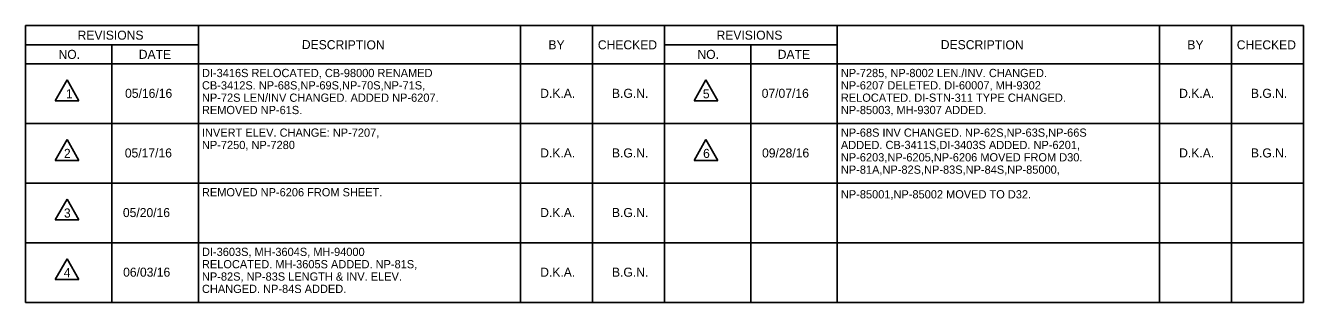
# Model space of a CAD drawing. Extents: x 260980 to 263829, y 322034 to 323393.
# Drawn here: x 263208 to 263829, y 322034 to 322169 of the extents above; entities that cross this region are included whole.
import ezdxf

# ---------------------------------------------------------------- set-up
doc = ezdxf.new("R2010")
doc.units = 0
doc.layers.add('RD_SHT_TX', color=7, linetype='Continuous')

msp = doc.modelspace()

# ---------------------------------------------------------------- linework, layer by layer
at = {"layer": 'RD_SHT_TX'}
for p, q in [((263208.14, 322034.07), (263208.14, 322168.77)), ((263208.14, 322168.77), (263518.73, 322168.77)), ((263292.13, 322034.07), (263292.13, 322168.77)), ((263448.73, 322034.07), (263448.73, 322168.77)), ((263483.73, 322034.07), (263483.73, 322168.77)), ((263518.73, 322034.07), (263518.73, 322168.77)), ((263518.73, 322168.77), (263829.33, 322168.77)), ((263602.73, 322034.07), (263602.73, 322168.77)), ((263759.33, 322034.07), (263759.33, 322168.77)), ((263794.33, 322034.07), (263794.33, 322168.77)), ((263829.33, 322034.07), (263829.33, 322168.76)), ((263292.13, 322159.42), (263208.13, 322159.42)), ((263250.13, 322034.07), (263250.13, 322159.42)), ((263602.73, 322159.42), (263518.73, 322159.42)), ((263560.73, 322034.07), (263560.73, 322159.42)), ((263518.73, 322150.07), (263208.13, 322150.07)), ((263829.33, 322150.07), (263518.73, 322150.07)), ((263228.3, 322142.33), (263222.6, 322132.19)), ((263233.99, 322132.19), (263228.3, 322142.33)), ((263538.89, 322142.33), (263533.2, 322132.19)), ((263544.59, 322132.19), (263538.89, 322142.33)), ((263222.6, 322132.19), (263233.99, 322132.19)), ((263533.2, 322132.19), (263544.59, 322132.19)), ((263518.73, 322121.07), (263208.13, 322121.07)), ((263829.33, 322121.07), (263518.73, 322121.07)), ((263228.3, 322113.33), (263222.6, 322103.19)), ((263233.99, 322103.19), (263228.3, 322113.33)), ((263538.89, 322113.33), (263533.2, 322103.19)), ((263544.59, 322103.19), (263538.89, 322113.33)), ((263222.6, 322103.19), (263233.99, 322103.19)), ((263533.2, 322103.19), (263544.59, 322103.19)), ((263518.73, 322092.07), (263208.13, 322092.07)), ((263829.33, 322092.07), (263518.73, 322092.07)), ((263228.3, 322084.33), (263222.6, 322074.19)), ((263233.99, 322074.19), (263228.3, 322084.33)), ((263222.6, 322074.19), (263233.99, 322074.19)), ((263518.73, 322063.07), (263208.13, 322063.07)), ((263829.33, 322063.07), (263518.73, 322063.07)), ((263228.3, 322055.33), (263222.6, 322045.19)), ((263233.99, 322045.19), (263228.3, 322055.33)), ((263222.6, 322045.19), (263233.99, 322045.19)), ((263518.73, 322034.07), (263208.13, 322034.07)), ((263829.33, 322034.07), (263518.73, 322034.07))]:
    msp.add_line(p, q, dxfattribs=at)

# ---------------------------------------------------------------- texts
for s, p in [('REVISIONS', (263233.42, 322161.89)), ('REVISIONS', (263544.02, 322161.89)), ('CHECKED', (263486.34, 322157.19)), ('CHECKED', (263796.93, 322157.19)), ('NO.', (263224.16, 322152.54)), ('NO.', (263534.75, 322152.54)), ('1', (263227.76, 322133.37)), ('5', (263537.39, 322133.37)), ('2', (263226.79, 322104.37)), ('6', (263537.49, 322104.37)), ('3', (263226.79, 322075.37)), ('4', (263226.68, 322046.37))]:
    msp.add_text(s, height=4.4, dxfattribs=at).set_placement(p)
for s, height, rotation, p in [('DESCRIPTION', 4.4083, 359.72458, (263342.43, 322157.31)), ('BY', 4.408, 359.72458, (263462.29, 322157.23)), ('DESCRIPTION', 4.4083, 359.72458, (263653.03, 322157.31)), ('BY', 4.408, 359.72458, (263772.89, 322157.23)), ('DATE', 4.408, 359.72458, (263263.16, 322152.57)), ('DATE', 4.408, 359.72458, (263573.76, 322152.57)), ('DI-3416S RELOCATED, CB-98000 RENAMED', 4, 360, (263293.89, 322143.68)), ('NP-7285, NP-8002 LEN./INV. CHANGED.', 4, 360, (263604.48, 322143.68)), ('CB-3412S. NP-68S,NP-69S,NP-70S,NP-71S,', 4, 360, (263293.89, 322137.68)), ('NP-6207 DELETED. DI-60007, MH-9302', 4, 360, (263604.48, 322137.68)), ('05/16/16', 4.4, 360, (263256.52, 322133.6)), ('NP-72S LEN/INV CHANGED. ADDED NP-6207.', 4, 360, (263293.89, 322131.68)), ('D.K.A.', 4.4, 360, (263458.32, 322133.6)), ('B.G.N.', 4.4, 360, (263493.2, 322133.6)), ('07/07/16', 4.4, 360, (263565.98, 322133.6)), ('RELOCATED. DI-STN-311 TYPE CHANGED.', 4, 360, (263604.48, 322131.68)), ('D.K.A.', 4.4, 360, (263768.92, 322133.6)), ('B.G.N.', 4.4, 360, (263803.8, 322133.6)), ('REMOVED NP-61S.', 4, 360, (263293.89, 322125.68)), ('NP-85003, MH-9307 ADDED.', 4, 360, (263604.48, 322125.68)), ('INVERT ELEV. CHANGE: NP-7207,', 4, 360, (263293.88, 322114.68)), ('NP-68S INV CHANGED. NP-62S,NP-63S,NP-66S', 4, 360, (263604.48, 322114.68)), ('NP-7250, NP-7280', 4, 360, (263293.88, 322108.68)), ('ADDED. CB-3411S,DI-3403S ADDED. NP-6201,', 4, 360, (263604.48, 322108.68)), ('05/17/16', 4.4, 360, (263256.38, 322104.6)), ('D.K.A.', 4.4, 360, (263458.32, 322104.6)), ('B.G.N.', 4.4, 360, (263493.2, 322104.6)), ('09/28/16', 4.4, 360, (263566.16, 322104.6)), ('NP-6203,NP-6205,NP-6206 MOVED FROM D30.', 4, 360, (263604.48, 322102.68)), ('D.K.A.', 4.4, 360, (263768.92, 322104.6)), ('B.G.N.', 4.4, 360, (263803.8, 322104.6)), ('NP-81A,NP-82S,NP-83S,NP-84S,NP-85000,', 4, 360, (263604.48, 322096.68)), ('REMOVED NP-6206 FROM SHEET.', 4, 360, (263293.89, 322085.68)), ('NP-85001,NP-85002 MOVED TO D32.', 4, 360, (263604.48, 322084.68)), ('05/20/16', 4.4, 360, (263255.46, 322075.6)), ('D.K.A.', 4.4, 360, (263458.32, 322075.6)), ('B.G.N.', 4.4, 360, (263493.2, 322075.6)), ('DI-3603S, MH-3604S, MH-94000', 4, 360, (263293.89, 322056.68)), ('RELOCATED. MH-3605S ADDED. NP-81S,', 4, 360, (263293.89, 322050.68)), ('06/03/16', 4.4, 360, (263255.56, 322046.6)), ('NP-82S, NP-83S LENGTH & INV. ELEV.', 4, 360, (263293.89, 322044.68)), ('D.K.A.', 4.4, 360, (263458.32, 322046.6)), ('B.G.N.', 4.4, 360, (263493.2, 322046.6)), ('CHANGED. NP-84S ADDED.', 4, 360, (263293.89, 322038.68))]:
    msp.add_text(s, height=height, rotation=rotation, dxfattribs=at).set_placement(p)

doc.saveas('drawing.dxf')
